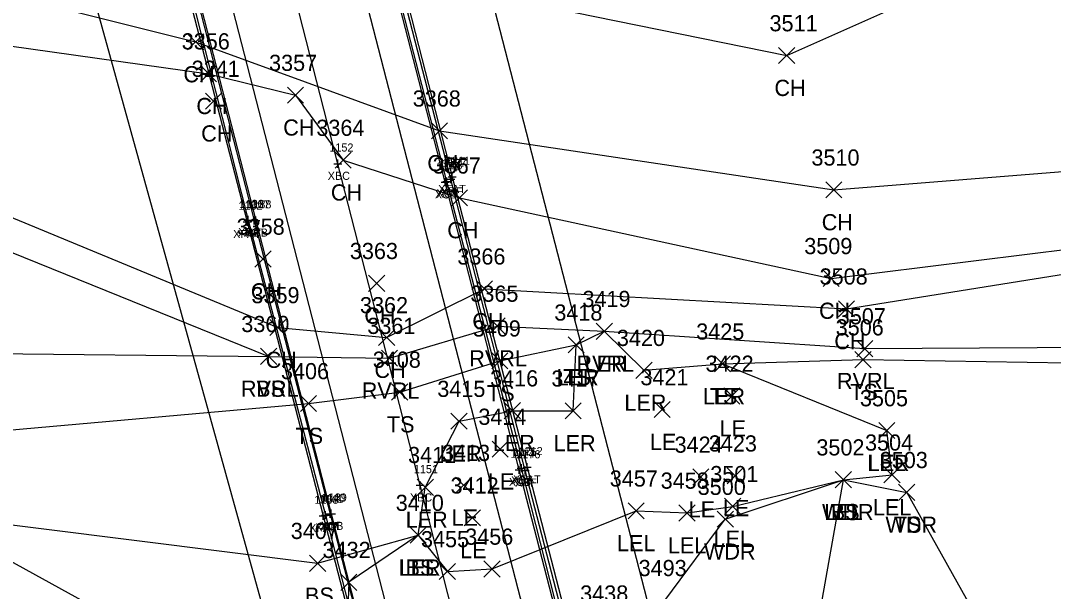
# Model space of a CAD drawing. Extents: x 1601151 to 1602912, y 499508 to 501770.
# Drawn here: x 1601546.4 to 1601674.2, y 500619.2 to 500689.8 of the extents above; entities that cross this region are included whole.
import ezdxf

# ---------------------------------------------------------------- set-up
doc = ezdxf.new("R2010")
doc.units = 0
for name, color, linetype in [('B_A', 7, 'Continuous'), ('B_I', 7, 'Continuous'), ('B_TIC', 7, 'Continuous'), ('BB', 7, 'Continuous'), ('BDC', 7, 'Continuous'), ('BELB', 7, 'Continuous'), ('BF', 7, 'Continuous'), ('BR', 7, 'Continuous'), ('L_A', 7, 'Continuous'), ('L_I', 7, 'Continuous'), ('L_TIC', 7, 'Continuous'), ('LARO', 7, 'Continuous'), ('LAWA', 7, 'Continuous'), ('LAWE', 7, 'Continuous'), ('LDEFAULT', 7, 'Continuous'), ('LELB', 7, 'Continuous'), ('UCO', 7, 'Continuous')]:
    doc.layers.add(name, color=color, linetype=linetype)

msp = doc.modelspace()

# ---------------------------------------------------------------- linework, layer by layer
at = {"layer": 'B_TIC'}
for p, q in [((1601585.66, 500672.12), (1601585.73, 500672.12)), ((1601599.63, 500670.2), (1601599.71, 500670.2)), ((1601599.8, 500670.49), (1601599.88, 500670.49)), ((1601598.92, 500669.82), (1601598.99, 500669.82)), ((1601599.15, 500669.93), (1601599.22, 500669.93)), ((1601574.57, 500665.15), (1601574.64, 500665.15)), ((1601575.3, 500665.09), (1601575.38, 500665.09)), ((1601575.51, 500665.1), (1601575.58, 500665.1)), ((1601574.43, 500664.92), (1601574.5, 500664.92)), ((1601608.36, 500634.47), (1601608.43, 500634.47)), ((1601609.07, 500634.57), (1601609.15, 500634.57)), ((1601608.07, 500634.25), (1601608.15, 500634.25)), ((1601608.83, 500634.18), (1601608.9, 500634.18)), ((1601595.83, 500632.34), (1601595.9, 500632.34)), ((1601583.83, 500628.56), (1601583.91, 500628.56)), ((1601584.1, 500628.64), (1601584.18, 500628.64)), ((1601584.69, 500628.8), (1601584.76, 500628.8)), ((1601584.84, 500628.83), (1601584.91, 500628.83))]:
    msp.add_line(p, q, dxfattribs=at)
for points in [[(1601585.15, 500672.12), (1601586.15, 500672.12)], [(1601585.65, 500671.62), (1601585.65, 500672.62)], [(1601598.91, 500669.32), (1601598.91, 500670.32)], [(1601599.13, 500670.2), (1601600.13, 500670.2)], [(1601599.14, 500669.43), (1601599.14, 500670.43)], [(1601599.3, 500670.49), (1601600.3, 500670.49)], [(1601599.63, 500669.7), (1601599.63, 500670.7)], [(1601599.8, 500669.99), (1601599.8, 500670.99)], [(1601598.41, 500669.82), (1601599.41, 500669.82)], [(1601598.64, 500669.93), (1601599.64, 500669.93)], [(1601574.06, 500665.15), (1601575.06, 500665.15)], [(1601574.42, 500664.42), (1601574.42, 500665.42)], [(1601574.56, 500664.65), (1601574.56, 500665.65)], [(1601574.8, 500665.09), (1601575.8, 500665.09)], [(1601575, 500665.1), (1601576, 500665.1)], [(1601575.3, 500664.59), (1601575.3, 500665.59)], [(1601575.5, 500664.6), (1601575.5, 500665.6)], [(1601573.92, 500664.92), (1601574.92, 500664.92)], [(1601607.85, 500634.47), (1601608.85, 500634.47)], [(1601608.07, 500633.75), (1601608.07, 500634.75)], [(1601608.35, 500633.97), (1601608.35, 500634.97)], [(1601608.57, 500634.57), (1601609.57, 500634.57)], [(1601608.82, 500633.68), (1601608.82, 500634.68)], [(1601609.07, 500634.07), (1601609.07, 500635.07)], [(1601607.57, 500634.25), (1601608.57, 500634.25)], [(1601608.32, 500634.18), (1601609.32, 500634.18)], [(1601595.32, 500632.34), (1601596.33, 500632.34)], [(1601595.82, 500631.84), (1601595.82, 500632.84)], [(1601584.68, 500628.3), (1601584.68, 500629.3)], [(1601584.83, 500628.33), (1601584.83, 500629.33)], [(1601583.33, 500628.56), (1601584.33, 500628.56)], [(1601583.6, 500628.64), (1601584.6, 500628.64)], [(1601583.83, 500628.06), (1601583.83, 500629.06)], [(1601584.1, 500628.14), (1601584.1, 500629.14)], [(1601584.18, 500628.8), (1601585.18, 500628.8)], [(1601584.33, 500628.83), (1601585.33, 500628.83)]]:
    msp.add_lwpolyline(points, dxfattribs=at)
at = {"layer": 'BB'}
for points in [[(1601612.43, 500602.27), (1601552.33, 500834.64)], [(1601596.6, 500598.19), (1601536.68, 500830.88)]]:
    msp.add_lwpolyline(points, dxfattribs=at)
at = {"layer": 'BDC'}
for points in [[(1601626.62, 500562.48), (1601618.76, 500592.93), (1601608.07, 500634.25), (1601598.91, 500669.82), (1601586.17, 500719.23), (1601573.53, 500768.43), (1601563.16, 500808.62), (1601554.18, 500843.36), (1601545.7, 500876.64)], [(1601627.36, 500562.65), (1601626.82, 500562.74), (1601626.57, 500563.06), (1601618.94, 500592.98), (1601608.35, 500634.47), (1601599.14, 500669.93), (1601586.41, 500719.22), (1601573.7, 500768.59), (1601563.41, 500808.68), (1601554.3, 500843.38), (1601545.84, 500876.67)], [(1601521.71, 500869.96), (1601522.4, 500870.19), (1601530.67, 500838.29), (1601539.74, 500803.09), (1601549.8, 500763.94), (1601562.9, 500713.2), (1601575.3, 500665.09), (1601584.68, 500628.8), (1601595.24, 500588.1), (1601603.29, 500556.62), (1601602.83, 500556.33)], [(1601522.54, 500870.25), (1601530.89, 500838.16), (1601539.77, 500803.18), (1601550.06, 500763.65), (1601563.09, 500713.39), (1601575.5, 500665.1), (1601584.83, 500628.83), (1601595.28, 500588.33), (1601603.43, 500556.59), (1601602.76, 500556.07)]]:
    msp.add_lwpolyline(points, dxfattribs=at)
at = {"layer": 'BELB'}
msp.add_lwpolyline([(1601614.12, 500560.68), (1601606.11, 500592.04), (1601595.82, 500632.34), (1601585.65, 500672.12), (1601574.35, 500716.24), (1601561.5, 500765.24), (1601551.33, 500804.52), (1601542.34, 500839.86), (1601533.48, 500873.11)], dxfattribs=at)
at = {"layer": 'BF'}
for points in [[(1601546.6, 500876.47), (1601555.12, 500843.83), (1601564.25, 500808.58), (1601574.55, 500768.92), (1601587.26, 500719.44), (1601599.8, 500670.49), (1601609.07, 500634.57), (1601619.78, 500593.21)], [(1601521.71, 500869.96), (1601529.93, 500837.54), (1601538.82, 500802.89), (1601549.01, 500763.54), (1601561.99, 500712.94), (1601574.42, 500664.92), (1601583.83, 500628.56), (1601594.34, 500587.94), (1601602.83, 500556.33)]]:
    msp.add_lwpolyline(points, dxfattribs=at)
at = {"layer": 'BR'}
for points in [[(1601626.89, 500563.91), (1601619.49, 500592.93), (1601608.82, 500634.18), (1601599.63, 500670.2), (1601586.94, 500719.23), (1601574.29, 500768.59), (1601563.98, 500808.59), (1601554.99, 500843.34), (1601546.61, 500875.69)], [(1601521.92, 500869.37), (1601530.02, 500838.06), (1601539.08, 500802.86), (1601549.33, 500763.87), (1601562.42, 500713.04), (1601574.56, 500665.15), (1601584.1, 500628.64), (1601594.6, 500587.84), (1601602.42, 500557.54)]]:
    msp.add_lwpolyline(points, dxfattribs=at)
at = {"layer": 'L_TIC'}
for points in [[(1601567.04, 500686.18), (1601569.04, 500688.18)], [(1601569.04, 500686.18), (1601567.04, 500688.18)], [(1601640.19, 500684.49), (1601642.19, 500686.49)], [(1601642.19, 500684.49), (1601640.19, 500686.49)], [(1601568.64, 500682.25), (1601570.64, 500684.25)], [(1601570.64, 500682.25), (1601568.64, 500684.25)], [(1601569.25, 500678.86), (1601571.25, 500680.86)], [(1601571.25, 500678.86), (1601569.25, 500680.86)], [(1601579.39, 500679.59), (1601581.39, 500681.59)], [(1601581.39, 500679.59), (1601579.39, 500681.59)], [(1601597.22, 500675.18), (1601599.22, 500677.18)], [(1601599.22, 500675.18), (1601597.22, 500677.18)], [(1601585.29, 500671.56), (1601587.29, 500673.56)], [(1601587.29, 500671.56), (1601585.29, 500673.56)], [(1601599.69, 500666.89), (1601601.69, 500668.89)], [(1601601.69, 500666.89), (1601599.69, 500668.89)], [(1601646.03, 500667.88), (1601648.03, 500669.88)], [(1601648.03, 500667.88), (1601646.03, 500669.88)], [(1601575.38, 500659.33), (1601577.38, 500661.33)], [(1601577.38, 500659.33), (1601575.38, 500661.33)], [(1601645.7, 500656.93), (1601647.7, 500658.93)], [(1601647.7, 500656.93), (1601645.7, 500658.93)], [(1601589.44, 500656.32), (1601591.44, 500658.32)], [(1601591.44, 500656.32), (1601589.44, 500658.32)], [(1601602.79, 500655.64), (1601604.79, 500657.64)], [(1601604.79, 500655.64), (1601602.79, 500657.64)], [(1601647.59, 500653.17), (1601649.59, 500655.17)], [(1601649.59, 500653.17), (1601647.59, 500655.17)], [(1601577.22, 500650.86), (1601579.22, 500652.86)], [(1601579.22, 500650.86), (1601577.22, 500652.86)], [(1601604.35, 500651.04), (1601606.35, 500653.04)], [(1601606.35, 500651.04), (1601604.35, 500653.04)], [(1601617.61, 500650.39), (1601619.61, 500652.39)], [(1601619.61, 500650.39), (1601617.61, 500652.39)], [(1601617.61, 500650.39), (1601619.61, 500652.39)], [(1601619.61, 500650.39), (1601617.61, 500652.39)], [(1601590.68, 500649.62), (1601592.68, 500651.62)], [(1601592.68, 500649.62), (1601590.68, 500651.62)], [(1601614.13, 500648.71), (1601616.13, 500650.71)], [(1601616.13, 500648.71), (1601614.13, 500650.71)], [(1601614.13, 500648.71), (1601616.13, 500650.71)], [(1601616.13, 500648.71), (1601614.13, 500650.71)], [(1601649.85, 500648.25), (1601651.85, 500650.25)], [(1601651.85, 500648.25), (1601649.85, 500650.25)], [(1601576.08, 500647.29), (1601578.08, 500649.29)], [(1601578.08, 500647.29), (1601576.08, 500649.29)], [(1601576.08, 500647.29), (1601578.08, 500649.29)], [(1601578.08, 500647.29), (1601576.08, 500649.29)], [(1601591.03, 500647.06), (1601593.03, 500649.06)], [(1601593.03, 500647.06), (1601591.03, 500649.06)], [(1601604.69, 500646.74), (1601606.69, 500648.74)], [(1601606.69, 500646.74), (1601604.69, 500648.74)], [(1601649.64, 500646.88), (1601651.64, 500648.88)], [(1601651.64, 500646.88), (1601649.64, 500648.88)], [(1601622.52, 500645.57), (1601624.52, 500647.57)], [(1601624.52, 500645.57), (1601622.52, 500647.57)], [(1601632.25, 500646.36), (1601634.25, 500648.36)], [(1601634.25, 500646.36), (1601632.25, 500648.36)], [(1601632.25, 500646.36), (1601634.25, 500648.36)], [(1601634.25, 500646.36), (1601632.25, 500648.36)], [(1601592.3, 500642.88), (1601594.3, 500644.88)], [(1601594.3, 500642.88), (1601592.3, 500644.88)], [(1601581, 500641.46), (1601583, 500643.46)], [(1601583, 500641.46), (1601581, 500643.46)], [(1601633.4, 500642.38), (1601635.4, 500644.38)], [(1601635.4, 500642.38), (1601633.4, 500644.38)], [(1601606.23, 500640.57), (1601608.23, 500642.57)], [(1601608.23, 500640.57), (1601606.23, 500642.57)], [(1601613.76, 500640.55), (1601615.76, 500642.55)], [(1601615.76, 500640.55), (1601613.76, 500642.55)], [(1601624.77, 500640.71), (1601626.77, 500642.71)], [(1601626.77, 500640.71), (1601624.77, 500642.71)], [(1601599.64, 500639.27), (1601601.64, 500641.27)], [(1601601.64, 500639.27), (1601599.64, 500641.27)], [(1601652.58, 500638.11), (1601654.58, 500640.11)], [(1601654.58, 500638.11), (1601652.58, 500640.11)], [(1601652.58, 500638.11), (1601654.58, 500640.11)], [(1601654.58, 500638.11), (1601652.58, 500640.11)], [(1601604.72, 500635.82), (1601606.72, 500637.82)], [(1601606.72, 500635.82), (1601604.72, 500637.82)], [(1601629.57, 500632.37), (1601631.57, 500634.37)], [(1601631.57, 500632.37), (1601629.57, 500634.37)], [(1601633.81, 500632.52), (1601635.81, 500634.52)], [(1601635.81, 500632.52), (1601633.81, 500634.52)], [(1601653.22, 500632.63), (1601655.22, 500634.63)], [(1601655.22, 500632.63), (1601653.22, 500634.63)], [(1601595.46, 500631.09), (1601597.46, 500633.09)], [(1601597.46, 500631.09), (1601595.46, 500633.09)], [(1601600.22, 500631.35), (1601602.22, 500633.35)], [(1601602.22, 500631.35), (1601600.22, 500633.35)], [(1601647.2, 500632.03), (1601649.2, 500634.03)], [(1601649.2, 500632.03), (1601647.2, 500634.03)], [(1601647.2, 500632.03), (1601649.2, 500634.03)], [(1601649.2, 500632.03), (1601647.2, 500634.03)], [(1601647.2, 500632.03), (1601649.2, 500634.03)], [(1601649.2, 500632.03), (1601647.2, 500634.03)], [(1601655.04, 500630.47), (1601657.04, 500632.47)], [(1601657.04, 500630.47), (1601655.04, 500632.47)], [(1601655.04, 500630.47), (1601657.04, 500632.47)], [(1601657.04, 500630.47), (1601655.04, 500632.47)], [(1601633.51, 500628.73), (1601635.51, 500630.73)], [(1601635.51, 500628.73), (1601633.51, 500630.73)], [(1601601.28, 500627.32), (1601603.28, 500629.32)], [(1601603.28, 500627.32), (1601601.28, 500629.32)], [(1601621.55, 500628.18), (1601623.55, 500630.18)], [(1601623.55, 500628.18), (1601621.55, 500630.18)], [(1601627.85, 500627.92), (1601629.85, 500629.92)], [(1601629.85, 500627.92), (1601627.85, 500629.92)], [(1601632.59, 500627.15), (1601634.59, 500629.15)], [(1601634.59, 500627.15), (1601632.59, 500629.15)], [(1601594.58, 500625.17), (1601596.58, 500627.17)], [(1601596.58, 500625.17), (1601594.58, 500627.17)], [(1601594.58, 500625.17), (1601596.58, 500627.17)], [(1601596.58, 500625.17), (1601594.58, 500627.17)], [(1601594.58, 500625.17), (1601596.58, 500627.17)], [(1601596.58, 500625.17), (1601594.58, 500627.17)], [(1601582.14, 500621.7), (1601584.14, 500623.7)], [(1601584.14, 500621.7), (1601582.14, 500623.7)], [(1601603.72, 500620.99), (1601605.72, 500622.99)], [(1601605.72, 500620.99), (1601603.72, 500622.99)], [(1601598.19, 500620.68), (1601600.19, 500622.68)], [(1601600.19, 500620.68), (1601598.19, 500622.68)], [(1601586.01, 500619.35), (1601588.01, 500621.35)], [(1601588.01, 500619.35), (1601586.01, 500621.35)], [(1601586.01, 500619.35), (1601588.01, 500621.35)], [(1601588.01, 500619.35), (1601586.01, 500621.35)]]:
    msp.add_lwpolyline(points, dxfattribs=at)
at = {"layer": 'LARO'}
for points in [[(1601595.58, 500626.17), (1601596.46, 500632.09), (1601600.64, 500640.27), (1601607.23, 500641.57), (1601614.76, 500641.55), (1601615.13, 500649.71), (1601618.61, 500651.39), (1601623.52, 500646.57), (1601633.25, 500647.36), (1601653.58, 500639.11)], [(1601595.58, 500626.17), (1601599.19, 500621.68), (1601604.72, 500621.99), (1601622.55, 500629.18), (1601628.85, 500628.92), (1601634.51, 500629.73), (1601648.2, 500633.03), (1601654.22, 500633.63), (1601653.58, 500639.11)]]:
    msp.add_lwpolyline(points, dxfattribs=at)
at = {"layer": 'LAWA'}
for points in [[(1601302.55, 500689.49), (1601363.58, 500662.81), (1601380.11, 500655.57), (1601400.84, 500652.59), (1601450.95, 500643.85), (1601476.8, 500629.17), (1601478.07, 500629.17), (1601496.83, 500637), (1601499.44, 500638.01), (1601508.97, 500634.75), (1601512.57, 500627.47), (1601537.32, 500627.23), (1601563.93, 500612.63), (1601565.22, 500607.85), (1601579.08, 500591.88), (1601571.6, 500572.54), (1601570.48, 500566.05)], [(1601626.12, 500618.11), (1601633.59, 500628.15), (1601648.2, 500633.03), (1601656.04, 500631.47), (1601665.92, 500613.83), (1601678.53, 500593.27), (1601702.45, 500561.86), (1601700.63, 500541.83), (1601700.97, 500520.51), (1601701.43, 500508.42), (1601692.75, 500493.59), (1601673.57, 500488.49), (1601667.99, 500487.13), (1601653.75, 500517.62), (1601642.44, 500550.9)]]:
    msp.add_lwpolyline(points, dxfattribs=at)
at = {"layer": 'LAWE'}
msp.add_lwpolyline([(1601306.18, 500751.33), (1601317.25, 500756.98), (1601367.83, 500763.3), (1601372.87, 500762.43), (1601412.18, 500735.73), (1601469.83, 500692.23), (1601501.36, 500678.91), (1601577.08, 500648.29), (1601592.03, 500648.06), (1601605.35, 500652.04), (1601618.61, 500651.39), (1601650.85, 500649.25), (1601686.37, 500649.48), (1601701.52, 500650.2), (1601728.46, 500647.17), (1601756.56, 500648.67), (1601769.4, 500643.2)], dxfattribs=at)
at = {"layer": 'LDEFAULT'}
for points in [[(1601337.45, 500787.94), (1601362.97, 500800.69), (1601393.84, 500792.74), (1601431.56, 500786.24), (1601466, 500759.52), (1601526, 500726.82), (1601566.27, 500697.9), (1601580.09, 500695.39), (1601593.87, 500695.15), (1601641.19, 500685.49), (1601672.03, 500699.21), (1601695.98, 500708.01), (1601703.42, 500706.03), (1601734.4, 500680.19), (1601767.36, 500664.87), (1601779.68, 500657.31)], [(1601339.09, 500785.52), (1601337.45, 500787.94), (1601364.5, 500789.17), (1601390.07, 500781.72), (1601419.33, 500750.23), (1601457.25, 500747.59), (1601513.71, 500700.8), (1601568.04, 500687.18), (1601598.22, 500676.18), (1601647.03, 500668.88), (1601695.93, 500672.79), (1601756.55, 500665.64), (1601778.58, 500654.09)], [(1601301.76, 500763.28), (1601339.09, 500785.52), (1601365.11, 500777.53), (1601390.18, 500773.26), (1601417.2, 500745.85), (1601452.03, 500737.65), (1601508.9, 500691.77), (1601569.64, 500683.25), (1601580.39, 500680.59), (1601586.29, 500672.56), (1601600.69, 500667.89), (1601646.7, 500657.93), (1601688.58, 500663.11)], [(1601303.68, 500759.4), (1601367.74, 500774.76), (1601385.3, 500764.32), (1601413.55, 500740.04), (1601448.35, 500721.35), (1601503.88, 500682.57), (1601578.22, 500651.86), (1601591.68, 500650.62), (1601603.79, 500656.64), (1601648.59, 500654.17), (1601682.93, 500659.64), (1601726.96, 500654.03), (1601736.69, 500654.19), (1601757.22, 500650.94), (1601774.12, 500647.76)]]:
    msp.add_lwpolyline(points, dxfattribs=at)
at = {"layer": 'LELB'}
for points in [[(1601519.49, 500637.84), (1601541.07, 500638.82), (1601582, 500642.46), (1601593.3, 500643.88), (1601605.69, 500647.74), (1601615.13, 500649.71)], [(1601500.91, 500649.1), (1601577.08, 500648.29)], [(1601633.25, 500647.36), (1601650.64, 500647.88), (1601686.17, 500647.33)], [(1601508.97, 500634.75), (1601537.69, 500628.42), (1601583.14, 500622.7), (1601595.58, 500626.17), (1601587.01, 500620.35)], [(1601643.34, 500605.61), (1601648.2, 500633.03)], [(1601587.01, 500620.35), (1601586.66, 500611.46), (1601589.52, 500603.91), (1601584.89, 500589.75), (1601583.23, 500572.75), (1601582.01, 500556.94), (1601586.09, 500551.38), (1601586.32, 500550.71)]]:
    msp.add_lwpolyline(points, dxfattribs=at)
at = {"layer": 'UCO'}
for points in [[(1601595.97, 500546.62), (1601489.93, 500928.89)], [(1601636.55, 500569.31), (1601558.4, 500871.75)]]:
    msp.add_lwpolyline(points, dxfattribs=at)

# ---------------------------------------------------------------- texts
at = {"layer": 'B_A'}
for s, p in [('XBC', (1601584.39, 500670.12)), ('XCB', (1601597.65, 500667.82)), ('XCT', (1601597.86, 500667.93)), ('XFAT', (1601598.06, 500668.49)), ('XRF', (1601598.39, 500668.2)), ('XFAT', (1601572.68, 500662.92)), ('XRF', (1601573.32, 500663.15)), ('XCT', (1601574.02, 500663.09)), ('XCB', (1601574.24, 500663.1)), ('XCB', (1601606.81, 500632.25)), ('XCT', (1601607.07, 500632.47)), ('XFAT', (1601607.33, 500632.57)), ('XRF', (1601607.58, 500632.18)), ('XBC', (1601594.56, 500630.34)), ('XFAT', (1601582.08, 500626.56)), ('XRF', (1601582.86, 500626.64)), ('XCT', (1601583.4, 500626.8)), ('XCB', (1601583.57, 500626.83))]:
    msp.add_text(s, height=1, dxfattribs=at).set_placement(p)
at = {"layer": 'B_I'}
for s, p in [('1152', (1601584.59, 500673.62)), ('1177', (1601598.57, 500671.7)), ('1211', (1601599.02, 500671.99)), ('1179', (1601597.85, 500671.32)), ('1178', (1601598.08, 500671.43)), ('1136', (1601573.47, 500666.65)), ('1137', (1601574.24, 500666.59)), ('1138', (1601574.44, 500666.6)), ('1162', (1601573.34, 500666.42)), ('1175', (1601607.29, 500635.97)), ('1212', (1601608.01, 500636.07)), ('1174', (1601607.01, 500635.75)), ('1176', (1601607.73, 500635.68)), ('1151', (1601595.05, 500633.84)), ('1163', (1601582.74, 500630.06)), ('1141', (1601583.32, 500630.14)), ('1140', (1601583.58, 500630.3)), ('1139', (1601583.77, 500630.33))]:
    msp.add_text(s, height=1, dxfattribs=at).set_placement(p)
at = {"layer": 'L_A'}
for s, p in [('CH', (1601566.53, 500682.18)), ('CH', (1601639.67, 500680.49)), ('CH', (1601568.13, 500678.25)), ('CH', (1601568.73, 500674.86)), ('CH', (1601578.88, 500675.59)), ('CH', (1601596.71, 500671.18)), ('CH', (1601584.78, 500667.56)), ('CH', (1601645.52, 500663.88)), ('CH', (1601599.18, 500662.89)), ('CH', (1601574.87, 500655.33)), ('CH', (1601645.19, 500652.93)), ('CH', (1601588.92, 500652.32)), ('CH', (1601602.28, 500651.64)), ('CH', (1601647.08, 500649.17)), ('CH', (1601576.71, 500646.86)), ('RVRL', (1601601.91, 500647.04)), ('RVRL', (1601615.17, 500646.39)), ('LER', (1601616.19, 500646.39)), ('CH', (1601590.17, 500645.62)), ('LER', (1601612.71, 500644.71)), ('TS', (1601613.54, 500644.71)), ('RVRL', (1601647.41, 500644.25)), ('RVRL', (1601573.65, 500643.29)), ('BS', (1601575.52, 500643.29)), ('RVRL', (1601588.6, 500643.06)), ('TS', (1601604.1, 500642.74)), ('TS', (1601649.05, 500642.88)), ('LER', (1601621.1, 500641.57)), ('LER', (1601630.83, 500642.36)), ('TS', (1601631.66, 500642.36)), ('TS', (1601591.71, 500638.88)), ('TS', (1601580.4, 500637.46)), ('LE', (1601632.88, 500638.38)), ('LER', (1601604.81, 500636.57)), ('LER', (1601612.34, 500636.55)), ('LE', (1601624.26, 500636.71)), ('LER', (1601598.23, 500635.27)), ('LER', (1601651.17, 500634.11)), ('LEL', (1601651.22, 500634.11)), ('LE', (1601604.21, 500631.82)), ('LE', (1601633.3, 500628.52)), ('LEL', (1601651.86, 500628.63)), ('LE', (1601599.71, 500627.35)), ('LE', (1601629.06, 500628.37)), ('WDR', (1601645.56, 500628.03)), ('LEL', (1601645.84, 500628.03)), ('BS', (1601646.64, 500628.03)), ('LER', (1601594.04, 500627.09)), ('WDR', (1601653.41, 500626.47)), ('TS', (1601654.45, 500626.47)), ('LEL', (1601632.14, 500624.73)), ('LEL', (1601620.19, 500624.18)), ('LEL', (1601626.49, 500623.92)), ('LE', (1601600.77, 500623.32)), ('WDR', (1601630.95, 500623.15)), ('LER', (1601593.16, 500621.17)), ('LEL', (1601593.22, 500621.17)), ('BS', (1601594.02, 500621.17)), ('BS', (1601581.58, 500617.7))]:
    msp.add_text(s, height=2, dxfattribs=at).set_placement(p)
at = {"layer": 'L_I'}
for s, p in [('3511', (1601639.06, 500688.49)), ('3356', (1601566.32, 500686.25)), ('3357', (1601577.13, 500683.59)), ('3241', (1601567.55, 500682.86)), ('3368', (1601594.91, 500679.18)), ('3364', (1601582.98, 500675.56)), ('3367', (1601597.38, 500670.89)), ('3510', (1601644.25, 500671.88)), ('3358', (1601573.12, 500663.33)), ('3509', (1601643.36, 500660.93)), ('3363', (1601587.13, 500660.32)), ('3366', (1601600.43, 500659.64)), ('3508', (1601645.26, 500657.17)), ('3359', (1601574.95, 500654.86)), ('3365', (1601602.04, 500655.04)), ('3419', (1601615.91, 500654.39)), ('3419', (1601615.91, 500654.39)), ('3362', (1601588.38, 500653.62)), ('3418', (1601612.43, 500652.71)), ('3418', (1601612.43, 500652.71)), ('3507', (1601647.51, 500652.25)), ('3360', (1601573.69, 500651.29)), ('3360', (1601573.69, 500651.29)), ('3361', (1601589.29, 500651.06)), ('3409', (1601602.34, 500650.74)), ('3425', (1601629.99, 500650.36)), ('3425', (1601629.99, 500650.36)), ('3506', (1601647.25, 500650.88)), ('3420', (1601620.17, 500649.57)), ('3408', (1601589.96, 500646.88)), ('3422', (1601631.14, 500646.38)), ('3406', (1601578.6, 500645.46)), ('3416', (1601604.48, 500644.57)), ('3417', (1601612.07, 500644.55)), ('3421', (1601623.08, 500644.71)), ('3415', (1601597.95, 500643.27)), ('3505', (1601650.25, 500642.11)), ('3505', (1601650.25, 500642.11)), ('3414', (1601603.03, 500639.82)), ('3424', (1601627.31, 500636.37)), ('3423', (1601631.55, 500636.52)), ('3504', (1601650.88, 500636.63)), ('3411', (1601594.33, 500635.09)), ('3413', (1601598.53, 500635.35)), ('3502', (1601644.86, 500636.03)), ('3502', (1601644.86, 500636.03)), ('3502', (1601644.86, 500636.03)), ('3503', (1601652.7, 500634.47)), ('3503', (1601652.7, 500634.47)), ('3501', (1601631.73, 500632.73)), ('3412', (1601599.59, 500631.32)), ('3457', (1601619.29, 500632.18)), ('3458', (1601625.59, 500631.92)), ('3500', (1601630.17, 500631.15)), ('3410', (1601592.8, 500629.17)), ('3410', (1601592.8, 500629.17)), ('3410', (1601592.8, 500629.17)), ('3407', (1601579.81, 500625.7)), ('3455', (1601595.93, 500624.68)), ('3456', (1601601.4, 500624.99)), ('3432', (1601583.75, 500623.35)), ('3432', (1601583.75, 500623.35)), ('3493', (1601622.86, 500621.11)), ('3493', (1601622.86, 500621.11)), ('3493', (1601622.86, 500621.11)), ('3438', (1601615.63, 500617.96))]:
    msp.add_text(s, height=2, dxfattribs=at).set_placement(p)

doc.saveas('drawing.dxf')
